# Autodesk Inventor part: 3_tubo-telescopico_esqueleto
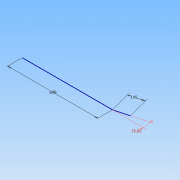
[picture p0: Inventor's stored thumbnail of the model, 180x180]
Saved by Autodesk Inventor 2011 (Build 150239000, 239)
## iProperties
Created: 2020-12
Part Number: 3_tubo-telescopico_esqueleto
Document SubType Name: Modeling
Designer: PC
Density: 1 g/cm^3
Author: PC
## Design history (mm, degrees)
sketch "Sketch1"
  geometry: L1 (0, 0)-(890, 0); L2 (890, 0)-(986.593, 25.882)
  constraints: 4 end point, 1 horizontal
  dimensions: "d0" = 890 dimension on L1.start L1.end L1 L2.end L2; "d0" = 890 distance of L1.start L1.end; "d1" = 15 deg angle of L1 L2; "d2" = 100 distance of L1.end L2.end
